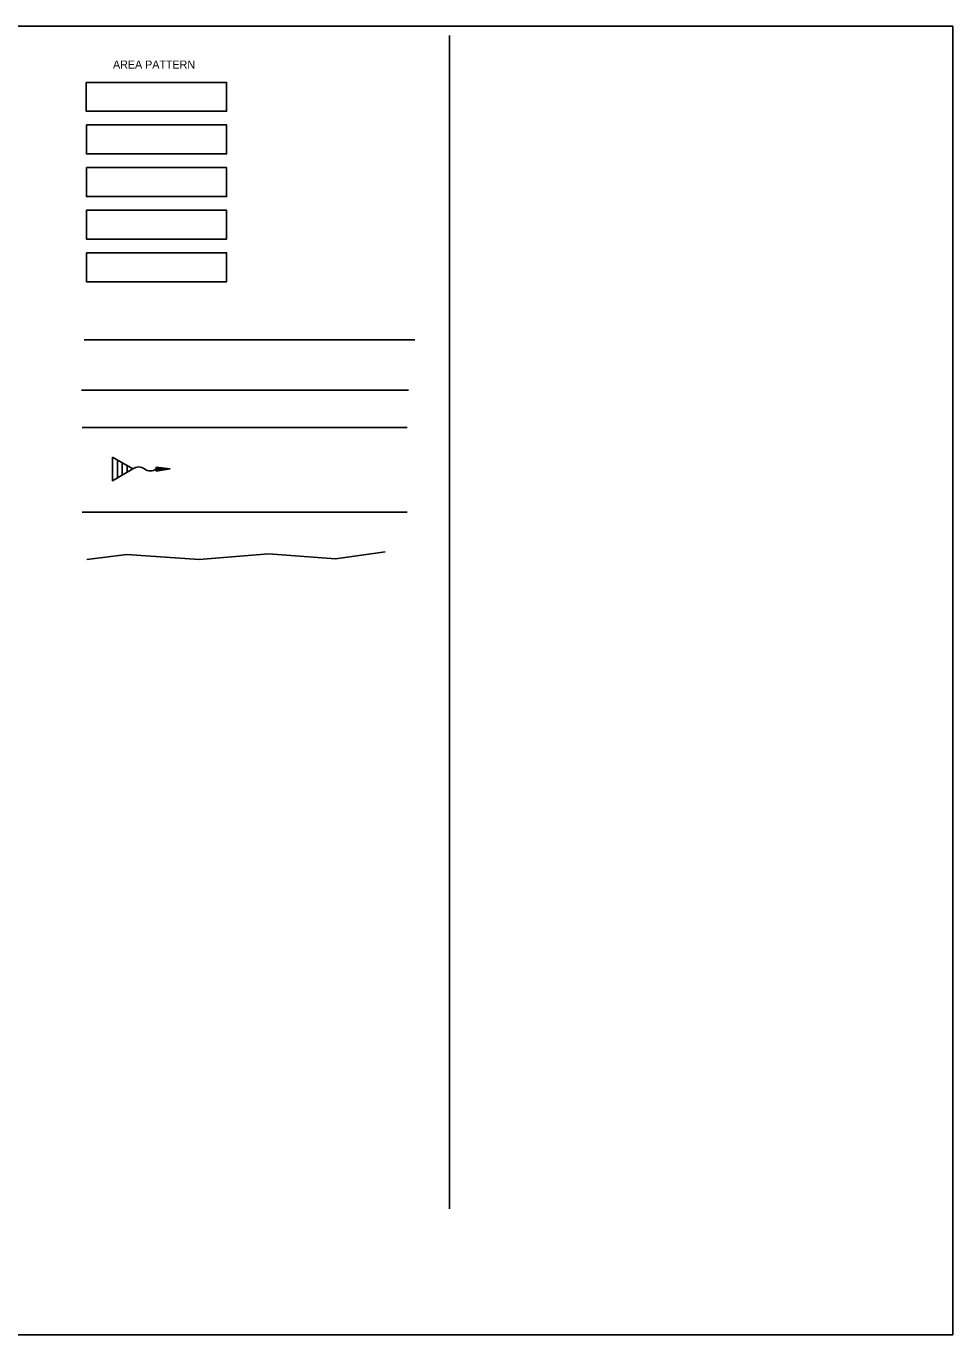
# Model space of a CAD drawing. Extents: x 0 to 2.72, y -0.06 to 0.86.
# Drawn here: x 2.111 to 2.725, y -0.002 to 0.865 of the extents above; entities that cross this region are included whole.
import ezdxf

# ---------------------------------------------------------------- set-up
doc = ezdxf.new("R2010")
doc.units = 0
for name, color, linetype in [('AUX_10', 7, 'Continuous'), ('D_Details', 7, 'Continuous'), ('Default', 7, 'Continuous'), ('P_EC_Check_Dams', 7, 'Continuous'), ('P_EC_Misc', 7, 'Continuous'), ('P_EC_Silt_Fence', 7, 'Continuous'), ('P_EC_Temporary_Diversion_Channel', 7, 'Continuous'), ('P_EC_Wattle', 7, 'Continuous')]:
    doc.layers.add(name, color=color, linetype=linetype)

msp = doc.modelspace()

# ---------------------------------------------------------------- linework, layer by layer
at = {"layer": 'D_Details'}
msp.add_line((2.39155, 0.85846), (2.39155, 0.0814), dxfattribs=at)
for points in [[(2.15094, 0.82741), (2.24383, 0.82741), (2.24383, 0.80823), (2.15094, 0.80823)], [(2.15095, 0.79918), (2.24384, 0.79918), (2.24384, 0.78001), (2.15095, 0.78001)], [(2.15096, 0.77096), (2.24384, 0.77096), (2.24384, 0.75179), (2.15096, 0.75179)], [(2.15097, 0.74274), (2.24385, 0.74274), (2.24385, 0.72356), (2.15097, 0.72356)], [(2.15097, 0.71452), (2.24386, 0.71452), (2.24386, 0.69534), (2.15097, 0.69534)]]:
    msp.add_lwpolyline(points, close=True, dxfattribs=at)
at = {"layer": 'Default'}
msp.add_lwpolyline([(1.42482, -0.00206), (2.72482, -0.00206), (2.72482, 0.86461), (1.42482, 0.86461)], close=True, dxfattribs=at)
at = {"layer": 'P_EC_Check_Dams'}
for p, q in [((2.16824, 0.57927), (2.16824, 0.56356)), ((2.18185, 0.57142), (2.16824, 0.57927)), ((2.17151, 0.57744), (2.17151, 0.5654)), ((2.17478, 0.57547), (2.17478, 0.56736)), ((2.17806, 0.57364), (2.17806, 0.56919)), ((2.20647, 0.57142), (2.1973, 0.57259)), ((2.1973, 0.57259), (2.1973, 0.56998)), ((2.16824, 0.56356), (2.18185, 0.57142)), ((2.1973, 0.57194), (2.20418, 0.57142)), ((2.1973, 0.57161), (2.20057, 0.57135)), ((2.1973, 0.57142), (2.20647, 0.57142)), ((2.1973, 0.56998), (2.20647, 0.57142)), ((2.20418, 0.57142), (2.1973, 0.57063)), ((2.20057, 0.57135), (2.1973, 0.57096))]:
    msp.add_line(p, q, dxfattribs=at)
msp.add_lwpolyline([(2.16824, 0.57927), (2.18185, 0.57142), (2.16824, 0.56356)], close=True, dxfattribs=at)
for centre, radius, start, end in [((2.18562, 0.56652), 0.00622, 52.04201, 128.0189), ((2.19336, 0.57664), 0.00653, 233.15309, 307.03039)]:
    msp.add_arc(centre, radius, start, end, dxfattribs=at)
at = {"layer": 'P_EC_Misc'}
for p, q in [((2.14818, 0.59887), (2.36333, 0.59887)), ((2.14818, 0.54269), (2.36333, 0.54269))]:
    msp.add_line(p, q, dxfattribs=at)
at = {"layer": 'P_EC_Silt_Fence'}
msp.add_spline([(2.14952, 0.65682), (2.22733, 0.65682), (2.30761, 0.65682), (2.36856, 0.65682)], degree=3, dxfattribs=at)
at = {"layer": 'P_EC_Temporary_Diversion_Channel'}
msp.add_spline([(2.14769, 0.62358), (2.24383, 0.62358), (2.36425, 0.62358)], degree=3, dxfattribs=at)
at = {"layer": 'P_EC_Wattle'}
msp.add_lwpolyline([(2.15117, 0.51144), (2.17769, 0.5147), (2.22561, 0.51144), (2.27167, 0.51517), (2.31587, 0.51191), (2.3489, 0.51656)], dxfattribs=at)

# ---------------------------------------------------------------- texts
at = {"layer": 'AUX_10'}
msp.add_text('AREA PATTERN', height=0.0052992, dxfattribs=at).set_placement((2.16863, 0.83656))

doc.saveas('drawing.dxf')
